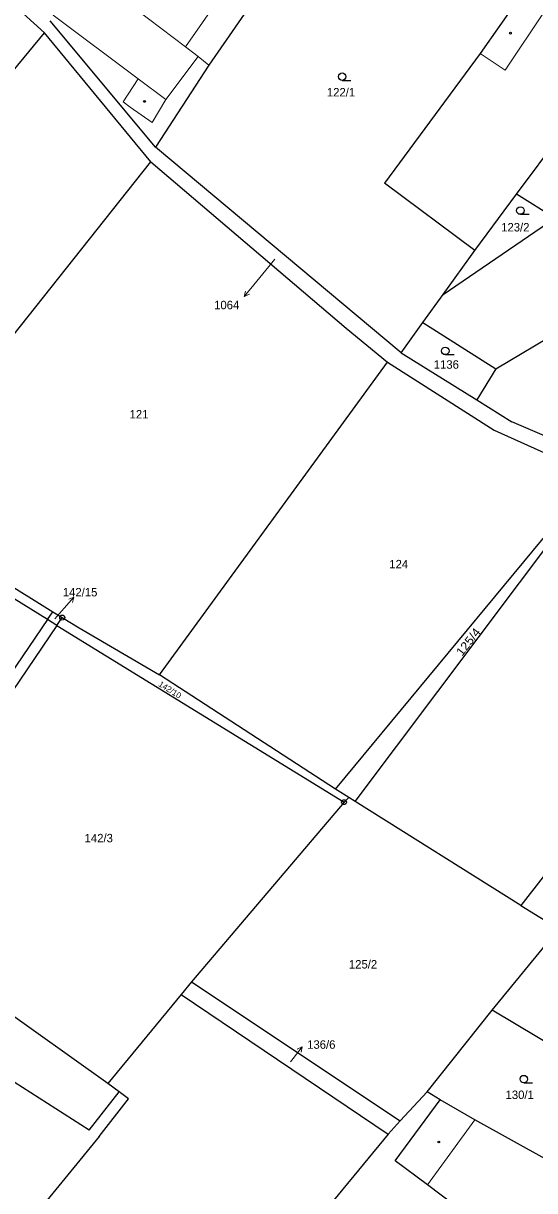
# Model space of a CAD drawing. Extents: x -694609 to -690140, y -1033292 to -1029794.
# Drawn here: x -692609.2 to -692506.4, y -1031705.3 to -1031470.7 of the extents above; entities that cross this region are included whole.
import ezdxf
from ezdxf.enums import TextEntityAlignment as Align

# ---------------------------------------------------------------- set-up
doc = ezdxf.new("R2010")
doc.units = 0
doc.header["$LTSCALE"] = 0.68
for name, color, linetype, lineweight in [('1', 7, 'Continuous', 25), ('3', 7, 'Continuous', 25), ('4', 7, 'Continuous', 13), ('5', 7, 'Continuous', 25), ('7', 7, 'Continuous', 13), ('8', 7, 'Continuous', 25)]:
    doc.layers.add(name, color=color, linetype=linetype, lineweight=lineweight)
doc.layers.add('2', color=7, linetype='Continuous')

msp = doc.modelspace()

# ---------------------------------------------------------------- linework, layer by layer
at = {"layer": '1'}
for p, q in [((-692604.9, -1031472.56), (-692615.76, -1031462.74)), ((-692509.09, -1031465.02), (-692517.3, -1031476.74)), ((-692582.62, -1031495.54), (-692603.77, -1031470.18)), ((-692668.37, -1031549.11), (-692604.9, -1031472.56)), ((-692583.56, -1031498.53), (-692604.9, -1031472.56)), ((-692517.3, -1031476.74), (-692536.58, -1031502.81)), ((-692509.98, -1031505.02), (-692489.17, -1031476.96)), ((-692533.23, -1031536.89), (-692582.62, -1031495.54)), ((-692638.3, -1031567.51), (-692583.56, -1031498.53)), ((-692583.56, -1031498.53), (-692544.24, -1031531.93)), ((-692518.37, -1031516.33), (-692536.58, -1031502.81)), ((-692518.37, -1031516.33), (-692509.98, -1031505.02)), ((-692502.29, -1031509.87), (-692509.98, -1031505.02)), ((-692524.76, -1031525.17), (-692502.29, -1031509.87)), ((-692524.76, -1031525.17), (-692518.37, -1031516.33)), ((-692528.82, -1031530.79), (-692524.76, -1031525.17)), ((-692514.18, -1031540.14), (-692489.29, -1031525.3)), ((-692544.24, -1031531.93), (-692535.95, -1031538.79)), ((-692533.23, -1031536.89), (-692528.82, -1031530.79)), ((-692528.82, -1031530.79), (-692514.18, -1031540.14)), ((-692533.23, -1031536.89), (-692517.99, -1031546.37)), ((-692581.77, -1031601.67), (-692535.95, -1031538.79)), ((-692535.95, -1031538.79), (-692514.5, -1031552.43)), ((-692514.18, -1031540.14), (-692517.99, -1031546.37)), ((-692517.99, -1031546.37), (-692510.92, -1031550.77)), ((-692491.61, -1031559.19), (-692510.92, -1031550.77)), ((-692514.5, -1031552.43), (-692494.27, -1031561.65)), ((-692546.37, -1031624.62), (-692494.27, -1031561.65)), ((-692542.42, -1031627.11), (-692493.57, -1031562)), ((-692604.32, -1031590.53), (-692629.81, -1031574.84)), ((-692628.76, -1031573.27), (-692603.26, -1031588.97)), ((-692455.1, -1031578.2), (-692509.11, -1031648.01)), ((-692604.32, -1031590.53), (-692603.26, -1031588.97)), ((-692603.26, -1031588.97), (-692601.35, -1031590.14)), ((-692604.32, -1031590.53), (-692648.12, -1031654.92)), ((-692602.42, -1031591.7), (-692604.32, -1031590.53)), ((-692602.42, -1031591.7), (-692601.35, -1031590.14)), ((-692601.35, -1031590.14), (-692597.95, -1031592.23)), ((-692602.42, -1031591.7), (-692641.18, -1031648.84)), ((-692602.42, -1031591.7), (-692544.69, -1031627.25)), ((-692597.95, -1031592.23), (-692581.77, -1031601.67)), ((-692546.37, -1031624.62), (-692581.77, -1031601.67)), ((-692543.72, -1031626.3), (-692546.37, -1031624.62)), ((-692543.72, -1031626.3), (-692544.69, -1031627.25)), ((-692542.42, -1031627.11), (-692543.72, -1031626.3)), ((-692544.69, -1031627.25), (-692575.35, -1031663.4)), ((-692509.11, -1031648.01), (-692542.42, -1031627.11)), ((-692592.18, -1031683.84), (-692641.18, -1031648.84)), ((-692509.11, -1031648.01), (-692501.49, -1031652.74)), ((-692514.87, -1031669.07), (-692501.49, -1031652.74)), ((-692575.35, -1031663.4), (-692577.43, -1031665.94)), ((-692575.35, -1031663.4), (-692533.41, -1031691.28)), ((-692577.43, -1031665.94), (-692592.18, -1031683.84)), ((-692577.43, -1031665.94), (-692535.83, -1031694)), ((-692527.97, -1031685.5), (-692514.87, -1031669.07)), ((-692491.42, -1031683.11), (-692514.87, -1031669.07)), ((-692595.92, -1031693.18), (-692615.73, -1031680.55)), ((-692589.91, -1031685.51), (-692592.18, -1031683.84)), ((-692595.92, -1031693.18), (-692589.91, -1031685.51)), ((-692593.96, -1031694.43), (-692588.03, -1031686.89)), ((-692588.03, -1031686.89), (-692589.91, -1031685.51)), ((-692534.42, -1031699.34), (-692525.37, -1031687.08)), ((-692527.97, -1031685.5), (-692533.41, -1031691.28)), ((-692525.37, -1031687.08), (-692527.97, -1031685.5)), ((-692518.37, -1031691.13), (-692525.37, -1031687.08)), ((-692503.62, -1031699.3), (-692518.37, -1031691.13)), ((-692593.96, -1031694.43), (-692626.76, -1031734.71)), ((-692527.93, -1031704.17), (-692534.42, -1031699.34)), ((-692505.25, -1031721.15), (-692527.93, -1031704.17))]:
    msp.add_line(p, q, dxfattribs=at)
for points in [[(-692560.11, -1031462), (-692571.88, -1031479.09), (-692582.62, -1031495.54)], [(-692533.41, -1031691.28), (-692535.83, -1031694), (-692554.95, -1031717.27)]]:
    msp.add_lwpolyline(points, dxfattribs=at)
at = {"layer": '3'}
for p, q in [((-692545.053, -1031482.14), (-692543.303, -1031482.14)), ((-692509.223, -1031509.07), (-692507.473, -1031509.07)), ((-692524.323, -1031537.28), (-692522.573, -1031537.28)), ((-692508.543, -1031683.67), (-692506.793, -1031683.67))]:
    msp.add_line(p, q, dxfattribs=at)
for centre in [(-692545.0529, -1031481.3898), (-692509.2229, -1031508.3198), (-692524.3229, -1031536.5298), (-692508.5429, -1031682.9198)]:
    msp.add_circle(centre, 0.75, dxfattribs=at)
at = {"layer": '4'}
for p, q in [((-692566.3, -1031460.66), (-692576.57, -1031475.41)), ((-692576.57, -1031475.41), (-692588.99, -1031466)), ((-692574.03, -1031477.34), (-692576.57, -1031475.41)), ((-692574.03, -1031477.34), (-692580.49, -1031486.01)), ((-692571.88, -1031479.09), (-692574.03, -1031477.34)), ((-692586.1, -1031481.81), (-692589.08, -1031486.48)), ((-692587.67, -1031487.53), (-692589.08, -1031486.48)), ((-692583.29, -1031490.62), (-692587.67, -1031487.53)), ((-692580.49, -1031486.01), (-692583.29, -1031490.62)), ((-692527.93, -1031704.17), (-692518.37, -1031691.13))]:
    msp.add_line(p, q, dxfattribs=at)
for points in [[(-692580.49, -1031486.01), (-692586.1, -1031481.81), (-692603.15, -1031469.05)], [(-692504.17, -1031467.97), (-692512.31, -1031480.07), (-692517.3, -1031476.74)]]:
    msp.add_lwpolyline(points, dxfattribs=at)
at = {"layer": '5'}
for centre in [(-692511.2268, -1031472.6492), (-692584.8068, -1031486.3692), (-692525.6368, -1031695.5692)]:
    msp.add_circle(centre, 0.175, dxfattribs=at)
at = {"layer": '7'}
for p, q in [((-692564.739, -1031525.602), (-692563.719, -1031525.139)), ((-692599.011, -1031586.015), (-692600.046, -1031586.442)), ((-692553.082, -1031676.415), (-692554.094, -1031676.896))]:
    msp.add_line(p, q, dxfattribs=at)
for points in [[(-692558.59, -1031518.09), (-692562.85, -1031523.27), (-692564.739, -1031525.602), (-692564.497, -1031524.509)], [(-692602.86, -1031590.42), (-692600.98, -1031588.28), (-692599.011, -1031586.015), (-692599.29, -1031587.099)], [(-692555.46, -1031679.46), (-692554.93, -1031678.78), (-692553.082, -1031676.415), (-692553.304, -1031677.513)]]:
    msp.add_lwpolyline(points, dxfattribs=at)
at = {"layer": '8'}
for centre, radius in [((-692601.35, -1031590.1399), 0.5), ((-692601.35, -1031590.1399), 0.0303), ((-692544.69, -1031627.2499), 0.5), ((-692544.69, -1031627.2499), 0.0303)]:
    msp.add_circle(centre, radius, dxfattribs=at)

# ---------------------------------------------------------------- texts
at = {"layer": '2'}
for s, p in [('122/1', (-692545.29, -1031485.375)), ('123/2', (-692510.24, -1031512.515)), ('1136', (-692524.12, -1031540.115)), ('121', (-692585.909, -1031550.115)), ('124', (-692533.689, -1031580.245)), ('142/15', (-692597.76, -1031585.885)), ('142/3', (-692594.01, -1031635.325)), ('125/2', (-692540.86, -1031660.695)), ('130/1', (-692509.36, -1031686.925))]:
    msp.add_text(s, height=1.7, dxfattribs=at).set_placement(p, align=Align.CENTER)
msp.add_text('1064', height=1.7, dxfattribs=at).set_placement((-692565.75, -1031528.155), align=Align.RIGHT)
for s, height, rotation, width, p in [('125/4', 1.7, 52, 1.1, (-692519.0265, -1031595.5543)), ('142/10', 1.172, 328, 1.05, (-692579.996, -1031605.1473))]:
    msp.add_text(s, height=height, rotation=rotation, dxfattribs=dict(at, width=width)).set_placement(p, align=Align.CENTER)
msp.add_text('136/6', height=1.7, dxfattribs=at).set_placement((-692552.1, -1031676.825))

doc.saveas('drawing.dxf')
